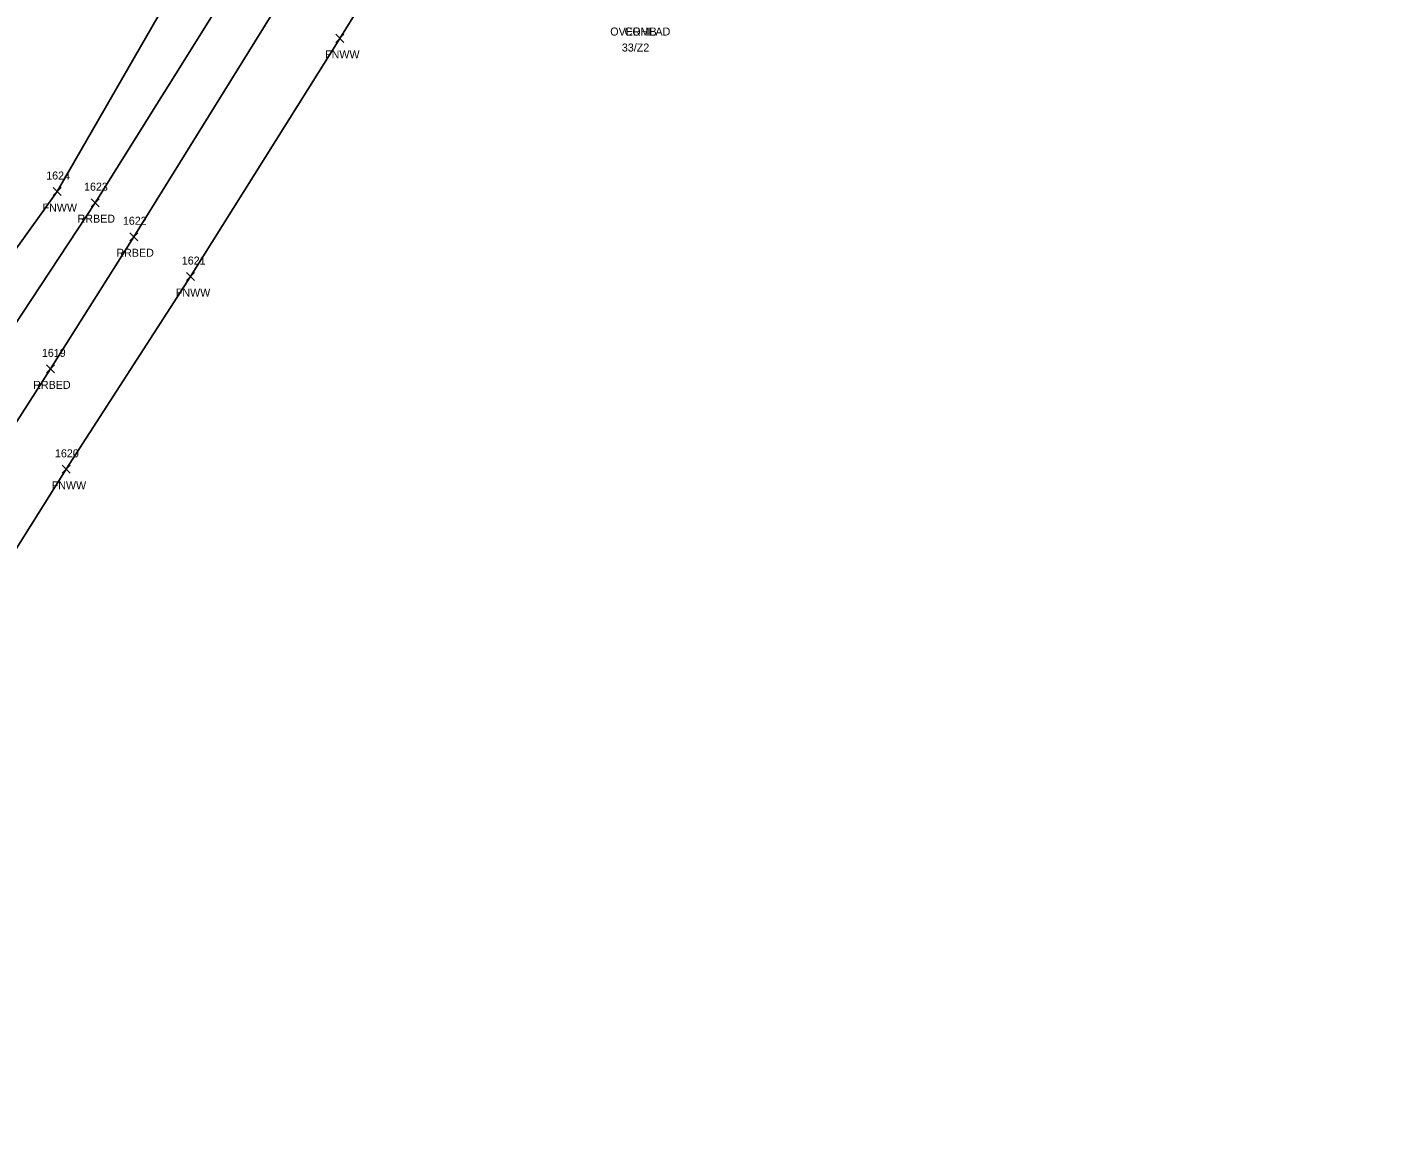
# Model space of a CAD drawing. Extents: x 1508122 to 1515053, y 865012 to 875267.
# Drawn here: x 1511162.4 to 1511499, y 869421.7 to 869697.2 of the extents above; entities that cross this region are included whole.
import ezdxf

# ---------------------------------------------------------------- set-up
doc = ezdxf.new("R2010")
doc.units = 0
for name, color, linetype in [('L_A', 7, 'Continuous'), ('L_I', 7, 'Continuous'), ('L_TIC', 7, 'Continuous'), ('LFNC', 7, 'Continuous'), ('R_A', 7, 'Continuous'), ('R_I', 7, 'Continuous'), ('R_TIC', 7, 'Continuous'), ('RRB', 7, 'Continuous'), ('U_A', 7, 'Continuous'), ('U_C', 7, 'Continuous')]:
    doc.layers.add(name, color=color, linetype=linetype)

msp = doc.modelspace()

# ---------------------------------------------------------------- linework, layer by layer
at = {"layer": 'L_TIC'}
for points in [[(1511239.52, 869693.32), (1511241.52, 869695.32)], [(1511241.52, 869693.32), (1511239.52, 869695.32)], [(1511168.91, 869655.03), (1511170.91, 869657.03)], [(1511170.91, 869655.03), (1511168.91, 869657.03)], [(1511202.22, 869633.78), (1511204.22, 869635.78)], [(1511204.22, 869633.78), (1511202.22, 869635.78)], [(1511171.19, 869585.61), (1511173.19, 869587.61)], [(1511173.19, 869585.61), (1511171.19, 869587.61)]]:
    msp.add_lwpolyline(points, dxfattribs=at)
at = {"layer": 'LFNC'}
for points in [[(1510487.97, 868590.92), (1510484.52, 868592.63), (1510520.32, 868648.34), (1510560.25, 868711.51), (1510582.03, 868746.35), (1510634, 868827.04), (1510686.82, 868909.82), (1510729.04, 868976.39), (1510801.8, 869091.1), (1510852.87, 869170.39), (1510912.76, 869264.38), (1510950.76, 869323.33), (1510992.09, 869387.13), (1511023.8, 869435.93), (1511065.2, 869500.26), (1511113.7, 869573.41), (1511147.07, 869624.31), (1511169.91, 869656.03), (1511204, 869715.28), (1511241.72, 869773.46)], [(1511062.28, 869416.08), (1511104.84, 869482.48), (1511145.99, 869545.07), (1511172.19, 869586.61), (1511203.22, 869634.78), (1511240.52, 869694.32), (1511269.35, 869740.84)]]:
    msp.add_lwpolyline(points, dxfattribs=at)
at = {"layer": 'R_TIC'}
for points in [[(1511178.37, 869652.25), (1511180.37, 869654.25)], [(1511180.37, 869652.25), (1511178.37, 869654.25)], [(1511188.07, 869643.73), (1511190.07, 869645.73)], [(1511190.07, 869643.73), (1511188.07, 869645.73)], [(1511167.28, 869610.72), (1511169.28, 869612.72)], [(1511169.28, 869610.72), (1511167.28, 869612.72)]]:
    msp.add_lwpolyline(points, dxfattribs=at)
at = {"layer": 'RRB'}
for points in [[(1510567.62, 868706.56), (1510590.3, 868741.33), (1510641.58, 868821.14), (1510694.12, 868904.03), (1510737.34, 868971.49), (1510810.55, 869083.19), (1510862.56, 869162.99), (1510923.65, 869257.51), (1510962.65, 869316.48), (1511003.03, 869380.52), (1511033.75, 869429.1), (1511076.21, 869490.94), (1511122.4, 869564.68), (1511156.76, 869618.82), (1511179.37, 869653.25), (1511213.93, 869708.42), (1511264.74, 869787.25), (1511286.05, 869815.23), (1511349.66, 869914.55), (1511393.09, 869983.89), (1511436.1, 870048.65), (1511490.68, 870132.35)], [(1510600.6, 868735.49), (1510651.55, 868814.96), (1510704.78, 868897.68), (1510748.11, 868964.85), (1510821.21, 869076.32), (1510873.49, 869156.69), (1510934.14, 869250.38), (1510973.56, 869310.54), (1511014.14, 869373.22), (1511046.88, 869423.36), (1511086.93, 869485.24), (1511132.78, 869556.33), (1511168.28, 869611.72), (1511189.07, 869644.73), (1511224.88, 869702.41), (1511269.99, 869771.64), (1511301.83, 869821.13), (1511359.57, 869908.74), (1511403.78, 869976.54), (1511445.67, 870042.93), (1511499.01, 870126.5)]]:
    msp.add_lwpolyline(points, dxfattribs=at)

# ---------------------------------------------------------------- texts
at = {"layer": 'L_A'}
for p in [(1511236.87, 869689.32), (1511166.26, 869651.03), (1511199.57, 869629.78), (1511168.54, 869581.61)]:
    msp.add_text('FNWW', height=2, dxfattribs=at).set_placement(p)
at = {"layer": 'L_I'}
for s, p in [('1624', (1511167.17, 869659.03)), ('1621', (1511201.05, 869637.78)), ('1620', (1511169.36, 869589.61))]:
    msp.add_text(s, height=2, dxfattribs=at).set_placement(p)
at = {"layer": 'R_A'}
for p in [(1511175.01, 869648.25), (1511184.71, 869639.73), (1511163.92, 869606.72)]:
    msp.add_text('RRBED', height=2, dxfattribs=at).set_placement(p)
at = {"layer": 'R_I'}
for s, p in [('1623', (1511176.63, 869656.25)), ('1622', (1511186.33, 869647.73)), ('1619', (1511166.09, 869614.72))]:
    msp.add_text(s, height=2, dxfattribs=at).set_placement(p)
at = {"layer": 'U_A'}
for s, p in [('OVERHEAD', (1511308.13, 869695.02)), ('COMB', (1511311.71, 869695.02))]:
    msp.add_text(s, height=2, dxfattribs=at).set_placement(p)
at = {"layer": 'U_C'}
msp.add_text('33/Z2', height=2, dxfattribs=at).set_placement((1511311.04, 869691.02))

doc.saveas('drawing.dxf')
